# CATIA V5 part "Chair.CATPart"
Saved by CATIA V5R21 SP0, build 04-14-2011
Part number: Part1
Material "DS Dark Red": density 7860 kg/m3, Young's modulus 2e+11 Pa, Poisson ratio 0.266
Bounding box of the stored display mesh (mm): x -45 to 45, y -45 to 68.664, z -24 to 88.216
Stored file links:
  G:\CATIA\Chair.CATPart
  C:\Program Files (x86)\Dassault Systemes\B21\intel_a\startup\materials\blue_env_512x512.jpg
  C:\Program Files (x86)\Dassault Systemes\B21\intel_a\startup\materials\green_env_512x512.jpg
  C:\Program Files (x86)\Dassault Systemes\B21\intel_a\startup\materials\alcantara.jpg
  C:\Program Files (x86)\Dassault Systemes\B21\intel_a\startup\materials\yellow_env_512x512.jpg
  C:\Program Files (x86)\Dassault Systemes\B21\intel_a\startup\materials\black_env_512x512.jpg
  C:\Program Files (x86)\Dassault Systemes\B21\intel_a\startup\materials\wall_of_bricks.jpg
  C:\Program Files (x86)\Dassault Systemes\B21\intel_a\startup\materials\turf.jpg
  C:\Program Files (x86)\Dassault Systemes\B21\intel_a\startup\materials\red_env_512x512.jpg
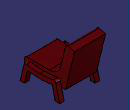
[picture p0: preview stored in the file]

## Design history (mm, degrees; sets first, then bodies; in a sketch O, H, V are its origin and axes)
Body1 (main body), material "DS Dark Red"
  Sketch1 on yz-plane, origin (0, 0, 0), H (0, 1, 0), V (0, 0, 1)
    line L1 (11.1075, 20) -> (-45, 20)
    line L2 (-45, 20) -> (-45, 0)
    line L3 (-45, 0) -> (48, 0)
    line L4 (48, 0) -> (68.6638, 84.5104)
    line L5 (68.6638, 84.5104) -> (49.2361, 89.2607)
    line L6 (49.2361, 89.2607) -> (37.3348, 40.5871)
    arc A1 centre (11.1075, 47) radius 27 from (11.1075, 20) to (37.3348, 40.5871) ccw
    length L3 = 93
    length L4 = 87
    length L2 = 20
    length L5 = 20
    radius A1 = 27
    angle L4 L5 = 90
    distance L2 V = 45
    horizontal: L1 H, L3 H
    vertical: L2 V
    parallelism: L6 L4
    tangency: A1 L1, A1 L6
    coincidence: L3 H
  Pad1: profile Sketch1, direction (1, 0, 0), length 35, mirrored extent
  Fillet1: radius 5, on edge [face of Pad1 from Sketch1.L6 | face of Pad1 from Sketch1.L5]; edge [face of Pad1 from Sketch1.L2 | face of Pad1 from Sketch1.L1]
  Sketch2 on end face of Pad1, origin (35, 0, 0), H (0, 1, 0), V (0, 0, 1)
    arc A1 centre (0, 185.4225) radius 173 from (-35, 16) to (0, 12.4225) ccw
    point P1 (0, 185.4225)
    point P2 (0, 12.4225)
    point P3 (-35, 16)
    arc A2 centre (0, 185.4225) radius 183 from (-27.861, 4.5559) to (0, 2.4225) ccw
    point P4 (0, 2.4225)
    line L1 (-35, 16) -> (-45, -24)
    point P5 (-45, -24)
    line L2 (-45, -24) -> (-35, -24)
    point P6 (-35, -24)
    line L3 (-35, -24) -> (-27.861, 4.5559)
    point P7 (-27.861, 4.5559)
    reference projected line E1 (-45, 0) -> (48, 0) from edge [face of Pad1 from Sketch1.L3 | end face of Pad1]
    reference projected line E2 (-45, 0) -> (48, 0) from edge [face of Pad1 from Sketch1.L3 | end face of Pad1]
    reference intersected line E3 through (0, 0) direction (0, 1) from zx-plane
    point P10 (0, 0)
    construction line L4 through (0, 0) direction (-1, 0)
    construction line L5 through (0, 0) direction (0, 1)
    point P11 (0, 12.4225)
    point P12 (35, 16)
    point P13 (0, 2.4225)
    point P14 (45, -24)
    point P15 (35, -24)
    point P16 (27.861, 4.5559)
    arc A3 centre (0, 185.4225) radius 173 from (35, 16) to (0, 12.4225) cw
    arc A4 centre (0, 185.4225) radius 183 from (27.861, 4.5559) to (0, 2.4225) cw
    line L6 (35, 16) -> (45, -24)
    line L7 (45, -24) -> (35, -24)
    line L8 (35, -24) -> (27.861, 4.5559)
    radius A1 = 173
    radius A2 = 183
    length L2 = 10
    distance V P6 = 35
    distance P3 E1 = 16
    distance L2 E2 = 24
    distance P3 P6 H = 0
    coincidence: P1 V, P2 V, P4 V, P2 P11, P4 P13
    horizontal: L2 H
    parallelism: L3 L1
    symmetry: O P10 E3, H L4 E3, V L5 E3, P2 P11 E3, P3 P12 E3, P4 P13 E3, P5 P14 E3, P6 P15 E3, P7 P16 E3, A1 A3 E3, A2 A4 E3, L1 L6 E3, L2 L7 E3, L3 L8 E3
  Pad2: profile Sketch2, direction (1, 0, 0), length 10
  Fillet2: radius 5, on edge [face of Pad2 from Sketch2.A3 | face of Pad2 from Sketch2.L6]; edge [face of Pad2 from Sketch2.L1 | face of Pad2 from Sketch2.A1]
  Mirror1: of Pad2, Fillet2, about yz-plane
